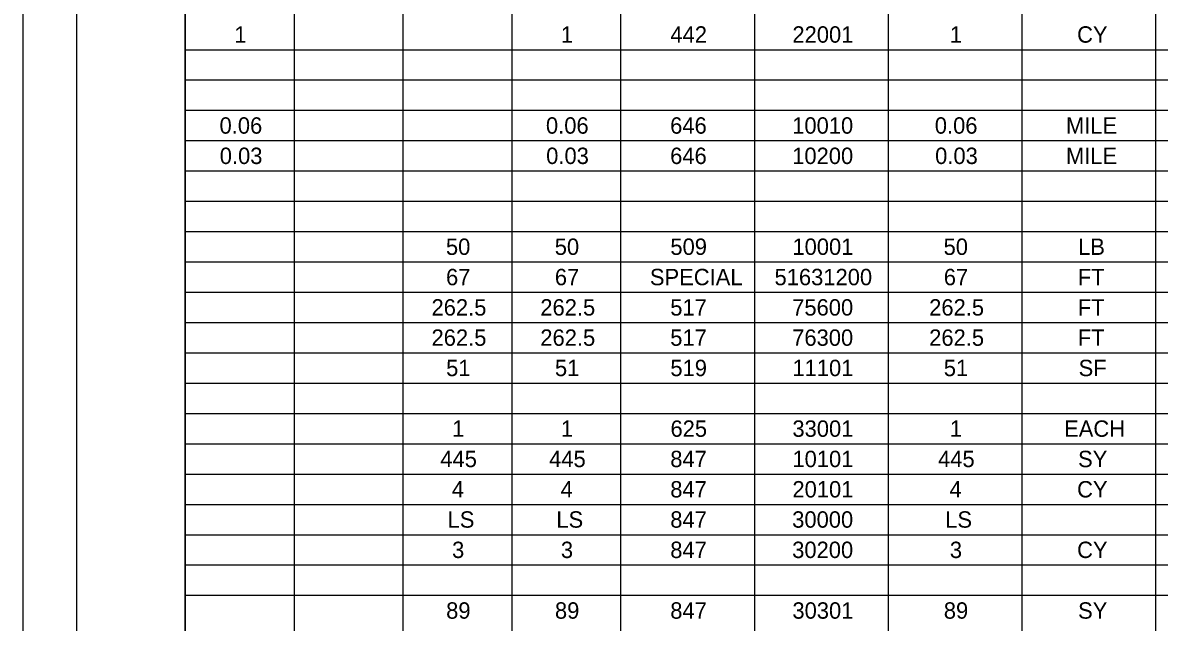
# Model space of a CAD drawing. Extents: x 0 to 34, y 0 to 22.
# Drawn here: x 0 to 10.49, y 10.9 to 16.43 of the extents above; entities that cross this region are included whole.
import ezdxf

# ---------------------------------------------------------------- set-up
doc = ezdxf.new("R2010")
doc.units = 0
for name, color, linetype in [('SH_Border', 7, 'Continuous'), ('SH_Cut_Line', 7, 'Continuous'), ('SH_Text', 7, 'Continuous')]:
    doc.layers.add(name, color=color, linetype=linetype)

msp = doc.modelspace()

# ---------------------------------------------------------------- linework, layer by layer
at = {"layer": 'SH_Border'}
for points in [[(0.5, 21.5), (1.5, 21.5), (1.5, 0.5), (0.5, 0.5)], [(1.5, 21.5), (33.5, 21.5), (33.5, 0.5), (1.5, 0.5)]]:
    msp.add_lwpolyline(points, close=True, dxfattribs=at)
at = {"layer": 'SH_Cut_Line'}
msp.add_lwpolyline([(0, 0), (34, 0), (34, 22), (0, 22)], close=True, dxfattribs=at)
at = {"layer": 'SH_Text'}
for p, q in [((1.5, 21.5), (1.5, 0.514)), ((4.512, 21.5), (4.512, 0.514)), ((5.516, 21.5), (5.516, 0.514)), ((6.751, 21.5), (6.751, 0.514)), ((7.985, 21.5), (7.985, 0.514)), ((9.22, 21.5), (9.22, 0.514)), ((10.454, 21.5), (10.454, 0.514)), ((2.504, 20.94), (2.504, 0.514)), ((3.508, 20.94), (3.508, 0.514)), ((1.5, 16.183), (32, 16.183)), ((1.5, 15.904), (32, 15.904)), ((1.5, 15.624), (32, 15.624)), ((1.5, 15.344), (32, 15.344)), ((1.5, 15.064), (32, 15.064)), ((1.5, 14.784), (32, 14.784)), ((1.5, 14.505), (32, 14.505)), ((1.5, 14.225), (32, 14.225)), ((1.5, 13.945), (32, 13.945)), ((1.5, 13.665), (32, 13.665)), ((1.5, 13.385), (32, 13.385)), ((1.5, 13.106), (32, 13.106)), ((1.5, 12.826), (32, 12.826)), ((1.5, 12.546), (32, 12.546)), ((1.5, 12.266), (32, 12.266)), ((1.5, 11.986), (32, 11.986)), ((1.5, 11.706), (32, 11.706)), ((1.5, 11.427), (32, 11.427)), ((1.5, 11.147), (32, 11.147))]:
    msp.add_line(p, q, dxfattribs=at)

# ---------------------------------------------------------------- texts
for s, height, p in [('1', 0.151, (1.953, 16.248)), ('1', 0.151, (4.966, 16.248)), ('442', 0.1514, (5.976, 16.248)), ('22001', 0.1514, (7.102, 16.248)), ('1', 0.151, (8.554, 16.248)), ('CY', 0.1514, (9.729, 16.248)), ('0.06', 0.1514, (1.816, 15.408)), ('0.06', 0.1514, (4.828, 15.408)), ('646', 0.1514, (5.974, 15.408)), ('10010', 0.1514, (7.1, 15.408)), ('0.06', 0.1514, (8.416, 15.408)), ('MILE', 0.1514, (9.626, 15.408)), ('0.03', 0.1514, (1.818, 15.128)), ('0.03', 0.1514, (4.83, 15.128)), ('646', 0.1514, (5.974, 15.128)), ('10200', 0.1514, (7.1, 15.128)), ('0.03', 0.1514, (8.419, 15.128)), ('MILE', 0.1514, (9.626, 15.128)), ('50', 0.1514, (3.905, 14.289)), ('50', 0.1514, (4.909, 14.289)), ('509', 0.1514, (5.976, 14.289)), ('10001', 0.1514, (7.102, 14.289)), ('50', 0.1514, (8.497, 14.289)), ('LB', 0.1514, (9.738, 14.289)), ('67', 0.1514, (3.906, 14.009)), ('67', 0.1514, (4.91, 14.009)), ('SPECIAL', 0.1514, (5.787, 14.009)), ('51631200', 0.1514, (6.937, 14.009)), ('67', 0.1514, (8.499, 14.009)), ('FT', 0.1514, (9.736, 14.009)), ('262.5', 0.1514, (3.772, 13.729)), ('262.5', 0.1514, (4.776, 13.729)), ('517', 0.1514, (5.975, 13.729)), ('75600', 0.1514, (7.1, 13.729)), ('262.5', 0.1514, (8.364, 13.729)), ('FT', 0.1514, (9.736, 13.729)), ('262.5', 0.1514, (3.772, 13.45)), ('262.5', 0.1514, (4.776, 13.45)), ('517', 0.1514, (5.975, 13.45)), ('76300', 0.1514, (7.1, 13.45)), ('262.5', 0.1514, (8.364, 13.45)), ('FT', 0.1514, (9.736, 13.45)), ('51', 0.1514, (3.907, 13.17)), ('51', 0.1514, (4.911, 13.17)), ('519', 0.1514, (5.976, 13.17)), ('11101', 0.1514, (7.102, 13.17)), ('51', 0.1514, (8.499, 13.17)), ('SF', 0.1514, (9.743, 13.17)), ('1', 0.151, (3.962, 12.61)), ('1', 0.151, (4.966, 12.61)), ('625', 0.1514, (5.977, 12.61)), ('33001', 0.1514, (7.102, 12.61)), ('1', 0.151, (8.554, 12.61)), ('EACH', 0.1514, (9.609, 12.61)), ('445', 0.1514, (3.853, 12.33)), ('445', 0.1514, (4.857, 12.33)), ('847', 0.1514, (5.975, 12.33)), ('10101', 0.1514, (7.102, 12.33)), ('445', 0.1514, (8.446, 12.33)), ('SY', 0.1514, (9.738, 12.33)), ('4', 0.151, (3.959, 12.05)), ('4', 0.151, (4.963, 12.05)), ('847', 0.1514, (5.975, 12.05)), ('20101', 0.1514, (7.102, 12.05)), ('4', 0.151, (8.551, 12.05)), ('CY', 0.1514, (9.729, 12.05)), ('LS', 0.1514, (3.92, 11.771)), ('LS', 0.1514, (4.924, 11.771)), ('847', 0.1514, (5.975, 11.771)), ('30000', 0.1514, (7.1, 11.771)), ('LS', 0.1514, (8.512, 11.771)), ('3', 0.151, (3.962, 11.491)), ('3', 0.151, (4.966, 11.491)), ('847', 0.1514, (5.975, 11.491)), ('30200', 0.1514, (7.1, 11.491)), ('3', 0.151, (8.555, 11.491)), ('CY', 0.1514, (9.729, 11.491)), ('89', 0.1514, (3.907, 10.931)), ('89', 0.1514, (4.911, 10.931)), ('847', 0.1514, (5.975, 10.931)), ('30301', 0.1514, (7.102, 10.931)), ('89', 0.1514, (8.499, 10.931)), ('SY', 0.1514, (9.738, 10.931))]:
    msp.add_text(s, height=height, dxfattribs=at).set_placement(p)

doc.saveas('drawing.dxf')
